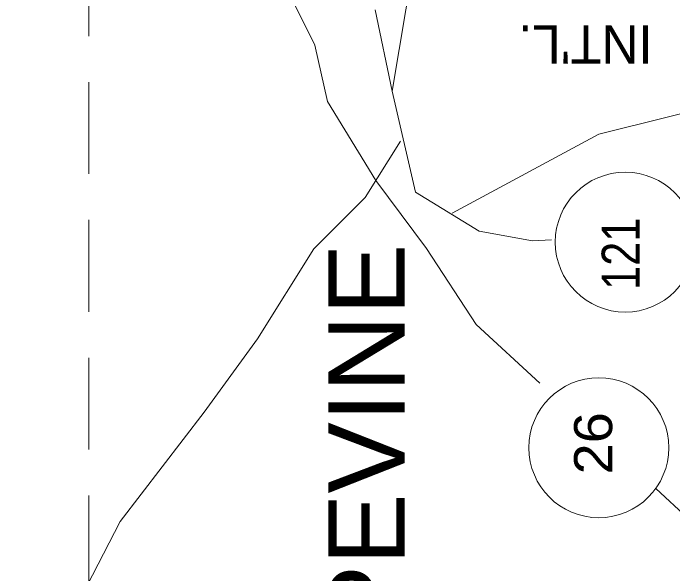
# Model space of a CAD drawing. Extents: x 2363323 to 2367082, y 6956018 to 6980837.
# Drawn here: x 2365838.7 to 2365927, y 6980657.7 to 6980732.7 of the extents above; entities that cross this region are included whole.
import ezdxf

# ---------------------------------------------------------------- set-up
doc = ezdxf.new("R2010")
doc.units = 0
doc.header["$LTSCALE"] = 4.1
doc.linetypes.add('MEDIUM_DASHED', pattern=[4.5, 3, -1.5])
doc.layers.add('62', color=7, linetype='Continuous', lineweight=13)
doc.layers.add('63', color=7, linetype='Continuous', lineweight=13)

msp = doc.modelspace()

# ---------------------------------------------------------------- linework, layer by layer
at = {"layer": '62', "linetype": 'MEDIUM_DASHED'}
msp.add_line((2365848.822, 6980834.218), (2365848.821, 6980385.954), dxfattribs=at)
at = {"layer": '62'}
for p, q in [((2365889.414, 6980722.292), (2365887.142, 6980733.186)), ((2365885.793, 6980708.072), (2365890.516, 6980715.586)), ((2365908.204, 6980702.244), (2365910.726, 6980702.379)), ((2365900.643, 6980691.062), (2365909.172, 6980683.228)), ((2365934.012, 6980660.367), (2365924.697, 6980669.121))]:
    msp.add_line(p, q, dxfattribs=at)
for points in [[(2365887.232, 6980710.322), (2365880.752, 6980720.898), (2365879.064, 6980728.456), (2365871.099, 6980744.57)], [(2365892.52, 6980708.793), (2365889.414, 6980722.292), (2365892.159, 6980738.832)], [(2365945.378, 6980723.576), (2365917.071, 6980716.532), (2365897.424, 6980705.979)], [(2365887.232, 6980710.322), (2365894.004, 6980701.254), (2365900.643, 6980691.062)], [(2365809.287, 6980449.612), (2365804.356, 6980460.212), (2365802.512, 6980474.5), (2365809.894, 6980490.59), (2365810.838, 6980501.526), (2365817.837, 6980515.14), (2365822.54, 6980524.522), (2365825.554, 6980532.603), (2365827.714, 6980543.964), (2365828.59, 6980553.189), (2365829.04, 6980565.342), (2365828.5, 6980579.562), (2365830.796, 6980597.678), (2365831.606, 6980609.468), (2365833.203, 6980622.902), (2365839.778, 6980637.732), (2365846.368, 6980651.814), (2365853.028, 6980664.688), (2365864.278, 6980679.314), (2365871.414, 6980689.148), (2365878.929, 6980701.188), (2365885.793, 6980708.072)], [(2365908.204, 6980702.244), (2365901.046, 6980703.572), (2365892.52, 6980708.793)]]:
    msp.add_lwpolyline(points, dxfattribs=at)
for centre in [(2365920.587, 6980702.089), (2365917.06, 6980674.561)]:
    msp.add_circle(centre, 9.364, dxfattribs=at)
at = {"layer": '63', "linetype": 'MEDIUM_DASHED'}
msp.add_line((2365848.822, 6980834.218), (2365848.821, 6980385.954), dxfattribs=at)
at = {"layer": '63'}
for p, q in [((2365889.414, 6980722.292), (2365887.142, 6980733.186)), ((2365885.793, 6980708.072), (2365890.516, 6980715.586)), ((2365908.204, 6980702.244), (2365910.726, 6980702.379)), ((2365900.643, 6980691.062), (2365909.172, 6980683.228)), ((2365934.012, 6980660.367), (2365924.697, 6980669.121))]:
    msp.add_line(p, q, dxfattribs=at)
for points in [[(2365887.232, 6980710.322), (2365880.752, 6980720.898), (2365879.064, 6980728.456), (2365871.099, 6980744.57)], [(2365892.52, 6980708.793), (2365889.414, 6980722.292), (2365892.159, 6980738.832)], [(2365945.378, 6980723.576), (2365917.071, 6980716.532), (2365897.424, 6980705.979)], [(2365887.232, 6980710.322), (2365894.004, 6980701.254), (2365900.643, 6980691.062)], [(2365809.287, 6980449.612), (2365804.356, 6980460.212), (2365802.512, 6980474.5), (2365809.894, 6980490.59), (2365810.838, 6980501.526), (2365817.837, 6980515.14), (2365822.54, 6980524.522), (2365825.554, 6980532.603), (2365827.714, 6980543.964), (2365828.59, 6980553.189), (2365829.04, 6980565.342), (2365828.5, 6980579.562), (2365830.796, 6980597.678), (2365831.606, 6980609.468), (2365833.203, 6980622.902), (2365839.778, 6980637.732), (2365846.368, 6980651.814), (2365853.028, 6980664.688), (2365864.278, 6980679.314), (2365871.414, 6980689.148), (2365878.929, 6980701.188), (2365885.793, 6980708.072)], [(2365908.204, 6980702.244), (2365901.046, 6980703.572), (2365892.52, 6980708.793)]]:
    msp.add_lwpolyline(points, dxfattribs=at)
for centre in [(2365920.587, 6980702.089), (2365917.06, 6980674.561)]:
    msp.add_circle(centre, 9.364, dxfattribs=at)

# ---------------------------------------------------------------- texts
at = {"layer": '62'}
msp.add_text("INT'L.", height=5.099, rotation=180, dxfattribs=at).set_placement((2365924.247, 6980731.094))
for s, height, width, p in [('121', 5.099, 0.85, (2365922.537, 6980695.698)), ('GRAPEVINE', 10.21, 1.05, (2365891.079, 6980618.242)), ('26', 5.099, 1.1, (2365918.846, 6980670.988))]:
    msp.add_text(s, height=height, rotation=90, dxfattribs=dict(at, width=width)).set_placement(p)
at = {"layer": '63'}
msp.add_text("INT'L.", height=5.099, rotation=180, dxfattribs=at).set_placement((2365924.247, 6980731.094))
for s, height, width, p in [('121', 5.099, 0.85, (2365922.537, 6980695.698)), ('GRAPEVINE', 10.21, 1.05, (2365891.079, 6980618.242)), ('26', 5.099, 1.1, (2365918.846, 6980670.988))]:
    msp.add_text(s, height=height, rotation=90, dxfattribs=dict(at, width=width)).set_placement(p)

doc.saveas('drawing.dxf')
